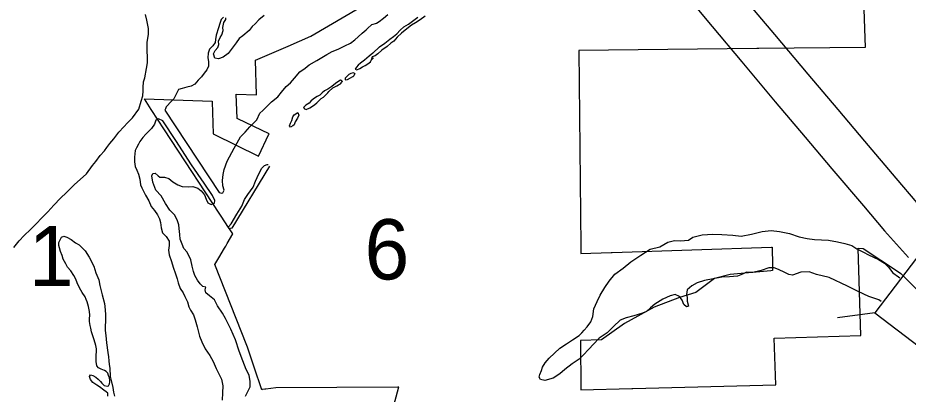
# Model space of a CAD drawing. Extents: x 1127717 to 1741049, y 2026793 to 2244711.
# Drawn here: x 1243058 to 1246182, y 2129649 to 2130968 of the extents above; entities that cross this region are included whole.
import ezdxf

# ---------------------------------------------------------------- set-up
doc = ezdxf.new("R2010")
doc.units = 0
for name, color, linetype in [('15', 7, 'Continuous'), ('20', 7, 'Continuous'), ('5', 7, 'Continuous'), ('6', 7, 'Continuous'), ('9', 7, 'Continuous')]:
    doc.layers.add(name, color=color, linetype=linetype)

msp = doc.modelspace()

# ---------------------------------------------------------------- linework, layer by layer
at = {"layer": '15'}
for points in [[(1244308.7, 2132633.3), (1244371, 2132566.7), (1244436.3, 2132499), (1244485, 2132440.8), (1244534.8, 2132370), (1244579.1, 2132302.4), (1244623.5, 2132228.8), (1244670.3, 2132162.7), (1244723.6, 2132094.4), (1244823, 2131973.7), (1244945.6, 2131829), (1245085.4, 2131658.1), (1245217, 2131501.5), (1245368.1, 2131321), (1245465.9, 2131207.5), (1245609.5, 2131034), (1245713.3, 2130910), (1245830, 2130770.8), (1245935.3, 2130646.3), (1246028.8, 2130535.9), (1246139.4, 2130405.9), (1246212.7, 2130319.6)], [(1244199.2, 2132530.8), (1244262.2, 2132463.4), (1244324.6, 2132398.7), (1244365.9, 2132349.3), (1244410.8, 2132285.7), (1244452.1, 2132222.5), (1244497.9, 2132146.5), (1244550, 2132073.2), (1244606.6, 2132000.5), (1244707.9, 2131877.6), (1244830.3, 2131733), (1244969.9, 2131562.4), (1245102, 2131405.1), (1245253.8, 2131223.9), (1245351.3, 2131110.7), (1245494.2, 2130938), (1245598.3, 2130813.6), (1245715.3, 2130674.2), (1245820.8, 2130549.4), (1245914.4, 2130438.8), (1246025.1, 2130308.8), (1246099.5, 2130221.1), (1246183.1, 2130127.3)]]:
    msp.add_lwpolyline(points, dxfattribs=at)
at = {"layer": '20'}
msp.add_line((1246065.3, 2129934.2), (1245934.4, 2129916.6), dxfattribs=at)
msp.add_lwpolyline([(1246222.7, 2129814.1), (1246583, 2130286.3), (1246425.6, 2130406.4), (1246065.3, 2129934.2)], close=True, dxfattribs=at)
at = {"layer": '6'}
for points in [[(1246008.2, 2131533.6), (1246031.7, 2130864.2), (1245658.1, 2130860.4), (1245654.9, 2130860.4), (1245651.8, 2130860.4), (1245027, 2130854), (1245034.1, 2130166.3), (1245034.1, 2130164.6), (1245034.1, 2130163), (1245034.3, 2130141.9), (1245139.7, 2130145.3), (1245142, 2130145.4), (1245144.3, 2130145.5), (1245702.3, 2130163.7), (1245705, 2130163.8), (1245706.1, 2130100.4), (1245706.4, 2130082), (1245700.5, 2130081.4), (1245557.4, 2130067.7), (1245503, 2130054.3), (1245437.9, 2130005.3), (1245379.7, 2129987.9), (1245290.7, 2129953.9), (1245186.7, 2129896), (1245106.2, 2129838.7), (1245033.1, 2129837.3), (1245034.2, 2129663.8), (1245212.9, 2129668.5), (1245214.3, 2129668.6), (1245215.8, 2129668.6), (1245717.6, 2129681.8), (1245712.6, 2129845.4), (1246016.5, 2129854.5), (1246007.4, 2130160.3), (1246025, 2130159.9), (1246086.4, 2130118.8), (1246130.5, 2130089.4), (1246156.6, 2130071.9), (1246211.7, 2130017)], [(1243763.5, 2130126.7), (1243783.5, 2130160.5), (1243787.8, 2130167.8), (1243793, 2130176.6), (1243813, 2130210.5), (1243812.6, 2130211.2), (1243791.1, 2130243.9), (1243790.5, 2130244.8), (1243789.9, 2130245.7), (1243573, 2130575.9), (1243548.3, 2130613.5), (1243529, 2130643.1), (1243526.7, 2130646.7), (1243502.5, 2130683.9), (1243739.8, 2130676.6), (1243739.9, 2130673.7), (1243743.3, 2130561.5), (1243745.6, 2130560.4), (1243902.4, 2130482.8), (1243939.5, 2130560), (1243940.1, 2130561.4), (1243829.8, 2130614.5), (1243827.5, 2130615.6), (1243825, 2130700.7), (1243896.2, 2130698.5), (1243892.5, 2130820), (1244006.6, 2130869), (1244087, 2130903.6), (1244319.8, 2131042.3)], [(1244349.4, 2129505.1), (1244394, 2129670.2), (1244394.8, 2129673.2), (1244394.6, 2129673.2), (1244392, 2129673.2), (1243963.5, 2129671.1), (1243928.3, 2129666.3), (1243926.8, 2129666.1), (1243925.3, 2129665.9), (1243916, 2129664.6), (1243914, 2129664.3), (1243887.9, 2129743.3), (1243864.7, 2129813.5), (1243862.2, 2129819.7), (1243749.5, 2130103), (1243763.5, 2130126.7)]]:
    msp.add_lwpolyline(points, dxfattribs=at)
at = {"layer": '9'}
for points in [[(1243043.8, 2130162.6), (1243062.7, 2130186.1), (1243080.7, 2130205.5), (1243102.7, 2130226.1), (1243123.6, 2130246.6), (1243141.1, 2130266), (1243164.1, 2130288.6), (1243185, 2130311.6), (1243208.3, 2130336.2), (1243228.8, 2130355.7), (1243256.1, 2130382.9), (1243299.1, 2130421.5), (1243320.9, 2130450.1), (1243331.5, 2130464.8), (1243347, 2130485.2), (1243362.1, 2130501.6), (1243370.3, 2130513.3), (1243381.4, 2130528.1), (1243395, 2130543.9), (1243412.9, 2130566.9), (1243430.4, 2130586.3), (1243443.1, 2130599.7), (1243461.1, 2130618.1), (1243483.3, 2130647.7), (1243491.1, 2130676.4), (1243496.7, 2130695.1), (1243498.3, 2130712.6), (1243498.5, 2130724.1), (1243499.5, 2130743.7), (1243504.1, 2130758.3), (1243509.4, 2130791), (1243512.9, 2130811.1), (1243513.3, 2130834.1), (1243511.9, 2130849.6), (1243511.7, 2130881.7), (1243516.5, 2130910.8), (1243516.5, 2130931.3), (1243511.3, 2130959.8), (1243506.8, 2130979.7)], [(1243780.5, 2130970.1), (1243771.3, 2130961.9), (1243766.6, 2130948.3), (1243762, 2130933.2), (1243754.1, 2130907.4), (1243752, 2130892.4), (1243751.2, 2130881.3), (1243742.5, 2130869.6), (1243730.8, 2130858.3), (1243725.7, 2130844.7), (1243725.1, 2130828.1), (1243727.9, 2130814.7), (1243726.8, 2130798.6), (1243722.1, 2130785.5), (1243711.9, 2130774.3), (1243702.7, 2130761), (1243691, 2130749.2), (1243678.9, 2130735.4), (1243666, 2130728.6), (1243651.2, 2130725.3), (1243635.3, 2130720.4), (1243621.9, 2130716.5), (1243613.8, 2130700.8), (1243605.7, 2130684.6), (1243593.5, 2130672.3), (1243581.9, 2130660), (1243578.5, 2130655.9), (1243576.6, 2130649.4), (1243574.7, 2130644.3)], [(1243923.1, 2130976.5), (1243903.5, 2130961), (1243891.4, 2130947.2), (1243880.6, 2130938.5), (1243869.5, 2130924.2), (1243847.5, 2130905.6), (1243835.2, 2130895.8), (1243824.1, 2130880.6), (1243807.2, 2130857.1), (1243796.5, 2130843.4), (1243778.9, 2130829.9), (1243762.6, 2130824), (1243749.5, 2130827.2), (1243745.2, 2130841.6), (1243750.9, 2130853.3), (1243760.1, 2130864), (1243763.4, 2130875.1), (1243762.6, 2130886.1), (1243767.8, 2130899.2), (1243774, 2130908.4), (1243778.7, 2130923.5), (1243777.4, 2130934), (1243781.5, 2130951.6), (1243788.7, 2130962.3), (1243788.1, 2130968.8)], [(1244487.5, 2130974.1), (1244470.4, 2130961.6), (1244453.2, 2130950.6), (1244440, 2130942.2), (1244423.4, 2130930.2), (1244404.9, 2130914.1), (1244389.8, 2130900.7), (1244377.7, 2130886.3), (1244367.4, 2130879), (1244354.8, 2130867.6), (1244335.7, 2130854.5), (1244322.1, 2130842.6), (1244312.3, 2130834.8), (1244301.4, 2130831), (1244298.2, 2130820.2)], [(1244356.1, 2130978.3), (1244341.9, 2130966.4), (1244326.3, 2130953.9), (1244317, 2130948.6), (1244299.7, 2130943.4)], [(1244304.1, 2130843.9), (1244327.9, 2130866.3), (1244345.9, 2130879.9), (1244364, 2130893.4), (1244376.7, 2130902.3), (1244387.9, 2130912.6), (1244399.5, 2130925), (1244412.7, 2130936.9), (1244429.4, 2130945.9), (1244443.6, 2130956.3), (1244461.6, 2130970.9)], [(1243574.7, 2130644.3), (1243764.8, 2130356.4), (1243772.9, 2130353.1), (1243777.8, 2130354.7), (1243782.6, 2130364.4), (1243778.2, 2130379.3), (1243776.8, 2130398.3), (1243778.8, 2130419.4), (1243782.8, 2130436.5), (1243793.1, 2130465.8), (1243801.2, 2130481), (1243818, 2130510.9), (1243828.5, 2130529.7), (1243840, 2130551.5), (1243855.6, 2130567.4), (1243872.6, 2130585.8), (1243890.1, 2130603.7), (1243896.4, 2130610.9), (1243907.9, 2130633.7), (1243917.6, 2130643.9), (1243933.2, 2130658.3), (1243948.8, 2130674.2), (1243970.4, 2130691.3), (1243984, 2130707.6), (1243999.9, 2130727.5), (1244015.1, 2130740.9), (1244028.7, 2130757.2), (1244048.1, 2130778.7), (1244066.3, 2130792.2), (1244081, 2130803), (1244107, 2130819.2), (1244125.3, 2130829.6), (1244142.5, 2130840), (1244161.2, 2130850), (1244182, 2130858.5), (1244206.1, 2130869.6), (1244225.4, 2130879.1), (1244241.1, 2130891.4), (1244252.8, 2130902.2), (1244267, 2130914.1), (1244280.6, 2130926.4), (1244287, 2130931.6), (1244299.7, 2130943.4)], [(1244304.1, 2130843.9), (1244290.8, 2130834), (1244274.7, 2130819.6), (1244261, 2130809.3), (1244252.2, 2130802.6), (1244246.3, 2130795.9), (1244242.5, 2130788.8), (1244247.6, 2130786.5), (1244257.9, 2130790.2), (1244268.3, 2130796), (1244277.2, 2130800.7), (1244286.5, 2130806.9), (1244295.3, 2130814.1), (1244298.2, 2130820.2), (1244306, 2130827.9)], [(1244240.4, 2130772.8), (1244234.9, 2130775.1), (1244226.9, 2130773.4), (1244220, 2130769.3), (1244213.7, 2130763.6), (1244206.9, 2130756.4), (1244207, 2130750.9), (1244215.4, 2130752.1), (1244225.8, 2130757.4), (1244233.7, 2130762.1), (1244237.1, 2130765.2)], [(1244196.1, 2130746.7), (1244190.1, 2130749.5), (1244181.2, 2130743.8), (1244172.9, 2130737.6), (1244160.1, 2130727.8), (1244145.9, 2130718), (1244134, 2130712.7), (1244126.7, 2130705), (1244118, 2130696.8), (1244108.6, 2130692.5), (1244096.3, 2130684.2), (1244087, 2130676.5), (1244080.2, 2130668.8), (1244069.4, 2130662.1), (1244061.1, 2130653.4), (1244064.7, 2130649.4), (1244070.2, 2130647.1), (1244082.6, 2130652.9), (1244091.9, 2130659.1), (1244100.3, 2130664.8), (1244107.6, 2130670.5), (1244114.4, 2130677.7), (1244118.3, 2130681.2), (1244123.2, 2130685.9), (1244131.1, 2130690.6), (1244138.9, 2130698.3), (1244145.7, 2130704.9), (1244149.6, 2130710), (1244164.2, 2130722.9), (1244170.1, 2130726.5), (1244177.6, 2130729.7), (1244184, 2130732.9), (1244190.4, 2130737), (1244195.7, 2130743.2)], [(1244196.1, 2130746.7), (1244195.7, 2130743.2)], [(1244240.4, 2130772.8), (1244237.1, 2130765.2)], [(1244040.6, 2130635.8), (1244043.8, 2130626.9), (1244040, 2130616.3), (1244031.9, 2130603.6), (1244028.1, 2130593.5), (1244023.2, 2130589.4), (1244015.3, 2130584.7), (1244011.2, 2130589.1), (1244015, 2130599.2), (1244019.3, 2130608.8), (1244023, 2130620.9), (1244028.3, 2130628)], [(1244028.3, 2130628), (1244040.6, 2130635.8)], [(1243567.6, 2130607.6), (1243551.5, 2130614.2), (1243545.1, 2130611.1), (1243542.6, 2130609.5), (1243539.8, 2130602.4), (1243538, 2130595.9), (1243526.9, 2130580.1), (1243518.1, 2130570.9), (1243507.9, 2130560.6), (1243496.7, 2130548.4), (1243487, 2130535.1), (1243481.3, 2130525.5), (1243474.6, 2130512.8), (1243470.3, 2130502.7), (1243467.9, 2130480.1), (1243467.3, 2130463), (1243470.2, 2130446.6), (1243476, 2130434.7), (1243481.3, 2130419.8), (1243486.7, 2130402.9), (1243489.2, 2130382.4), (1243493.9, 2130372), (1243506, 2130346.3), (1243518, 2130326.1), (1243526.4, 2130307.2), (1243538.3, 2130292.5), (1243548.6, 2130277.2), (1243555.9, 2130263.4), (1243558.7, 2130250.9), (1243561.2, 2130232.4), (1243565.6, 2130214.5), (1243578.9, 2130201.3), (1243589.7, 2130185.6), (1243589.6, 2130170), (1243586.5, 2130153.4)], [(1243857.3, 2129641.6), (1243865.4, 2129657.4), (1243873.4, 2129674.6), (1243874, 2129693.6), (1243870, 2129715.1), (1243859.5, 2129734.8), (1243848.3, 2129765.1), (1243834.5, 2129799.8), (1243822.1, 2129838.6), (1243805.2, 2129876.2), (1243786.9, 2129913.4), (1243776.4, 2129933.1), (1243759.4, 2129958.3), (1243748.9, 2129980), (1243731.1, 2129993.6), (1243718.3, 2130004.4), (1243715.6, 2130014.8), (1243718.3, 2130024.4), (1243707.8, 2130026.6), (1243697.6, 2130035.9), (1243688.8, 2130048.7), (1243679.5, 2130064.5), (1243674.6, 2130078.4), (1243670.2, 2130097.8), (1243665.2, 2130119.8), (1243652, 2130146.5), (1243640.3, 2130159.2), (1243634.4, 2130175.1), (1243628.5, 2130192), (1243626.6, 2130208), (1243624.6, 2130229.9), (1243623.8, 2130242.9), (1243617.9, 2130260.3), (1243607.5, 2130277.1), (1243592.1, 2130294.3), (1243576.6, 2130316.9), (1243561, 2130344.1), (1243543, 2130363.7), (1243532.4, 2130392), (1243528.4, 2130413.9), (1243532.6, 2130423), (1243540.6, 2130423.2), (1243550.3, 2130413.9), (1243556.9, 2130409.6), (1243572.9, 2130410), (1243588, 2130404.8), (1243602.2, 2130393.6), (1243619.4, 2130383), (1243635.1, 2130376.4), (1243656, 2130375.4), (1243672.5, 2130376.3), (1243690.1, 2130370.7), (1243701.8, 2130362), (1243713.1, 2130347.7), (1243718.9, 2130332.8), (1243724.7, 2130319.9), (1243736.9, 2130313.7), (1243748.2, 2130318.5), (1243749.5, 2130327.5), (1243741.6, 2130345.4), (1243712.6, 2130388.7), (1243667.7, 2130452.8), (1243613.2, 2130537.6), (1243567.6, 2130607.6)], [(1243941.3, 2130448.2), (1243809.7, 2130230.3), (1243800.3, 2130228.1), (1243798.1, 2130235.6), (1243807.4, 2130246.3), (1243826.5, 2130280.3), (1243844.8, 2130307.8), (1243854.2, 2130331), (1243865.3, 2130349.3), (1243883.6, 2130374.3), (1243892.1, 2130395.5), (1243903.5, 2130420.8), (1243914, 2130440.6), (1243924.2, 2130450.3), (1243933.1, 2130454.1), (1243936.6, 2130454.1)], [(1245632.2, 2130210.1), (1245670.4, 2130218.7), (1245702.2, 2130223.1), (1245731.3, 2130219.5), (1245766.4, 2130212), (1245800.2, 2130200.9), (1245827.9, 2130194.2), (1245853.4, 2130191), (1245877.9, 2130190.2), (1245902.9, 2130188.4), (1245934, 2130182.3), (1245959.6, 2130177), (1245984.8, 2130169.7), (1246002.6, 2130158.7), (1246025.9, 2130146.4), (1246043.6, 2130137.4), (1246078.6, 2130120.4), (1246099.9, 2130108.5), (1246113.8, 2130093.4), (1246128.3, 2130073.8), (1246148.2, 2130060.3), (1246152.8, 2130056.6)], [(1243332.8, 2129762.9), (1243333.1, 2129774.4), (1243333.3, 2129783.9), (1243334.5, 2129799), (1243333.8, 2129808), (1243332.5, 2129819.5), (1243326, 2129838.8), (1243321.7, 2129853.3), (1243316.9, 2129866.7), (1243314.1, 2129880.1), (1243311.8, 2129889.6), (1243309.5, 2129903), (1243309.8, 2129913.1), (1243311, 2129925.1), (1243309.7, 2129939.1), (1243306.3, 2129955.5), (1243301.4, 2129972.4), (1243298.2, 2129980.4), (1243294.5, 2129990.3), (1243284.6, 2130005.6), (1243275.2, 2130021.9), (1243266.8, 2130039.2), (1243262, 2130052.1), (1243254.7, 2130065), (1243243.9, 2130080.7), (1243233.1, 2130094), (1243226.8, 2130105.4), (1243217.5, 2130121.7), (1243214.2, 2130134.6), (1243208.3, 2130149), (1243204, 2130161.4), (1243202.8, 2130170.4), (1243202.1, 2130179.9), (1243207.8, 2130192), (1243212.1, 2130199.6), (1243220, 2130202.3), (1243230.6, 2130199.1), (1243245.2, 2130191.4), (1243261, 2130179.8), (1243273.1, 2130172), (1243294.6, 2130151), (1243308.6, 2130129.3), (1243324.8, 2130097.7), (1243331.9, 2130073.8), (1243342, 2130049), (1243346.4, 2130030.1), (1243354.7, 2129997.2), (1243361.9, 2129966.9), (1243364.9, 2129943.9), (1243366.3, 2129926.9), (1243365.8, 2129906.9), (1243364.9, 2129884.3), (1243365.2, 2129872.3), (1243366.6, 2129854.3), (1243369.2, 2129828.4), (1243374, 2129794.9), (1243376.4, 2129779), (1243377.7, 2129765), (1243378.5, 2129752.5), (1243381.3, 2129739.5), (1243382.5, 2129710), (1243387.4, 2129692.1), (1243391.9, 2129671.7), (1243393.1, 2129663.7), (1243394.3, 2129655.7), (1243398.1, 2129641.8)], [(1245027.5, 2129854), (1245037.7, 2129863.3), (1245046, 2129872.6), (1245056.1, 2129884.4), (1245069.1, 2129902.3), (1245076, 2129921.5), (1245079.2, 2129948.2), (1245091, 2129973), (1245101.8, 2129995.9), (1245117.5, 2130022.4), (1245132.8, 2130045.4), (1245153.6, 2130069), (1245182.4, 2130090.9), (1245209.7, 2130112.7), (1245244.5, 2130135.7), (1245276.8, 2130156.7), (1245311.5, 2130165.7), (1245339.5, 2130181.1), (1245362.8, 2130187.8), (1245383.8, 2130185.9), (1245411.7, 2130189.2), (1245427.4, 2130199.6), (1245459.1, 2130207.1), (1245497.4, 2130210.2), (1245528.4, 2130208.6), (1245567.5, 2130205.7), (1245596.5, 2130202.5), (1245632.2, 2130210.1)], [(1243586.5, 2130153.4), (1243588.9, 2130137.5), (1243597.9, 2130114.2), (1243602.9, 2130093.7), (1243611.9, 2130070.4), (1243617.4, 2130052.5), (1243621.2, 2130039.1), (1243627.6, 2130019.7), (1243639, 2130003.5), (1243644.3, 2129990.6), (1243654.2, 2129972.8), (1243658.6, 2129954.4), (1243663.9, 2129943.5), (1243674.8, 2129926.7), (1243680.7, 2129909.8), (1243687.8, 2129884.5), (1243696, 2129852.1), (1243704.5, 2129832.3), (1243716.1, 2129807.5), (1243732.6, 2129784.4), (1243744.1, 2129762.6), (1243754.6, 2129738.9), (1243764.6, 2129718.1), (1243772.5, 2129700.7), (1243777.5, 2129677.8), (1243776.6, 2129653.8), (1243775.8, 2129627.7)], [(1246087.3, 2129974.1), (1246079.2, 2129979.7), (1246044.9, 2129991.2), (1246006.4, 2130009.1), (1245969.5, 2130027.1), (1245905.7, 2130057.3), (1245860.9, 2130068.5), (1245835.2, 2130077.8), (1245805.3, 2130075.9), (1245776.1, 2130066.5), (1245763.6, 2130068.2), (1245749.9, 2130075.8), (1245727.2, 2130086.1), (1245712, 2130091.2), (1245693.1, 2130091.2), (1245666.9, 2130081.9), (1245637.6, 2130075), (1245615.1, 2130076.9), (1245600.9, 2130069), (1245583.1, 2130061.9), (1245555.2, 2130060.1), (1245528.3, 2130059.3), (1245467.7, 2130047.6), (1245442, 2130039.3), (1245423.3, 2130028.3), (1245407.2, 2130014.8), (1245404.2, 2129998.7), (1245407, 2129987.7), (1245406.9, 2129974.2), (1245411.9, 2129957.8), (1245404.5, 2129954.6), (1245395.8, 2129963.4), (1245389.3, 2129978.7), (1245380.5, 2129991.5), (1245364.3, 2129998), (1245347, 2129993), (1245321.3, 2129981.7), (1245292.9, 2129963.9), (1245278.8, 2129951.4), (1245263.7, 2129938), (1245246.4, 2129931), (1245219.7, 2129923.2), (1245192.5, 2129915.9), (1245172.2, 2129907.8), (1245148.9, 2129886.1), (1245126.1, 2129863.9), (1245097.7, 2129844.5), (1245078.3, 2129823.4), (1245061.4, 2129806.4), (1245042, 2129785.8), (1245028.4, 2129771.4), (1245003.9, 2129754.7), (1244978, 2129735.4), (1244960, 2129719.8), (1244937, 2129705.2), (1244907.3, 2129696.8), (1244892.2, 2129700.3), (1244888, 2129708.2), (1244889.7, 2129717.3), (1244895.3, 2129732), (1244899.9, 2129743.6), (1244909, 2129758.9), (1244923, 2129774.9), (1244941.4, 2129792.9), (1244960.4, 2129810), (1244983.4, 2129825.2), (1245004.5, 2129838.8), (1245027.5, 2129854)], [(1243373.7, 2129641.7), (1243373.9, 2129652.2), (1243367.8, 2129657.1), (1243359.7, 2129662.9), (1243345, 2129674.1), (1243335.8, 2129679.9), (1243322.1, 2129690), (1243313.9, 2129700.4), (1243309.6, 2129710.8), (1243313, 2129716.4), (1243321, 2129714.6), (1243332.2, 2129708.3), (1243340.3, 2129701), (1243348, 2129693.2), (1243353.6, 2129687.3), (1243361.3, 2129679.5), (1243371.4, 2129676.2), (1243376.8, 2129677.3), (1243380.1, 2129685.4), (1243381, 2129691.4), (1243381.3, 2129697.5), (1243380.1, 2129705.4), (1243376.9, 2129713.9), (1243374.3, 2129721.8), (1243368.1, 2129728.2), (1243363, 2129732.1), (1243351, 2129736.3), (1243341.9, 2129740.6), (1243335.2, 2129748.4), (1243332.8, 2129762.9)]]:
    msp.add_lwpolyline(points, dxfattribs=at)

# ---------------------------------------------------------------- texts
at = {"layer": '5'}
for s, p in [('6', (1244274.9, 2130051)), ('1', (1243096.6, 2130027.6))]:
    msp.add_text(s, height=211.2, dxfattribs=at).set_placement(p)

doc.saveas('drawing.dxf')
